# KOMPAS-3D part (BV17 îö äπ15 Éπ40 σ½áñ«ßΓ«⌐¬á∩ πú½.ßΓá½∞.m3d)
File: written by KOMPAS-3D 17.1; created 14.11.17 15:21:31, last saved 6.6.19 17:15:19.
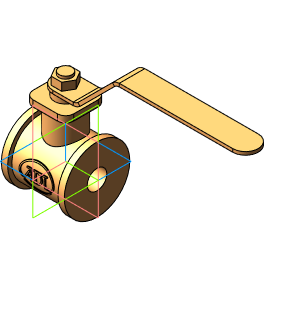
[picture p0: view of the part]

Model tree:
1. Операция без истории:1  (labels: Сталь 20  ГОСТ 1050-2013)

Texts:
  Линейный размер с обрывом
  Толщина листового тела
  Глубина освобождения сгиба
  Ширина освобождения сгиба
  BV17 МФ Ду15 Ру40 хладостойкая угл.сталь
  BV17 МФ Ду20 Ру40 хладостойкая угл.сталь
  BV17 МФ Ду25 Ру40 хладостойкая угл.сталь
  BV17 МФ Ду32 Ру40 хладостойкая угл.сталь
  BV17 МФ Ду40 Ру40 хладостойкая угл.сталь
  BV17 МФ Ду50 Ру40 хладостойкая угл.сталь
  BV17 МФ Ду65 Ру40 хладостойкая угл.сталь
  BV17 МФ Ду80 Ру40 хладостойкая угл.сталь
  BV17 МФ Ду100 Ру40 хладостойкая угл.сталь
